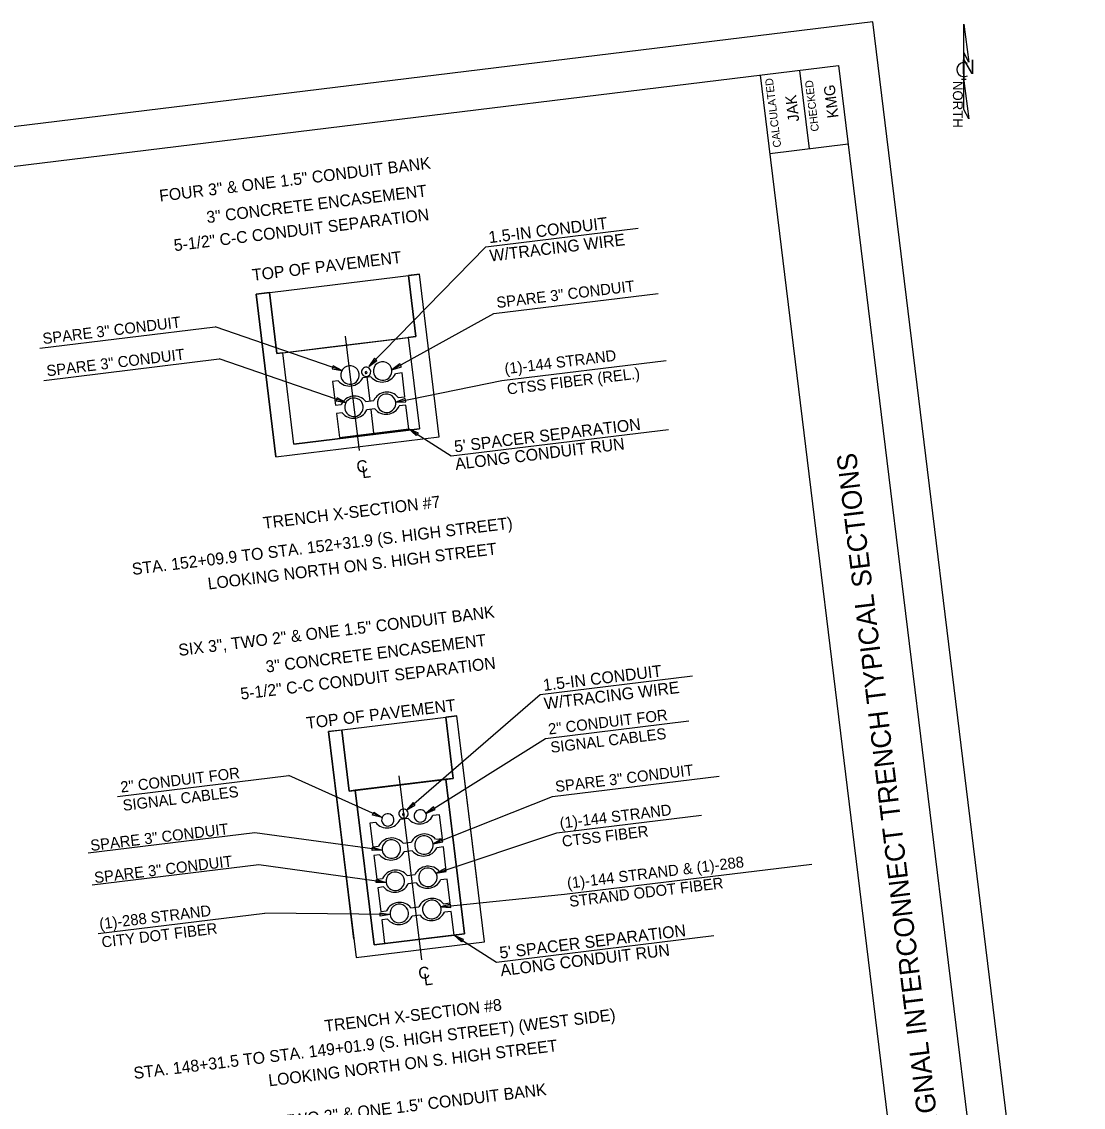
# Model space of a CAD drawing. Extents: x 91401 to 1830080, y 35587 to 712188.
# Drawn here: x 1828758 to 1829296, y 711584 to 712134 of the extents above; entities that cross this region are included whole.
import ezdxf

# ---------------------------------------------------------------- set-up
doc = ezdxf.new("R2010")
doc.units = 0
for name, color, linetype in [('Default', 7, 'Continuous'), ('SH_Border', 7, 'Continuous'), ('SH_Cut_Line', 7, 'Continuous'), ('SH_Data', 7, 'Continuous'), ('SH_Text', 7, 'Continuous')]:
    doc.layers.add(name, color=color, linetype=linetype)

# ---------------------------------------------------------------- blocks, each defined once
blk = doc.blocks.new('POINT_DISPLAY')
at = {"layer": 'Default'}
blk.add_line((0, 0), (0, 0), dxfattribs=at)

msp = doc.modelspace()

# ---------------------------------------------------------------- linework, layer by layer
at = {"layer": 'SH_Border'}
for p, q in [((1829234.27, 711273.16), (1829132.46, 712106.97)), ((1829152.31, 712109.39), (1829157.16, 712069.69)), ((1829137.3, 712067.26), (1829177.01, 712072.11))]:
    msp.add_line(p, q, dxfattribs=at)
for points in [[(1829235.72, 712108.85), (1829235.72, 712132.85), (1829238.12, 712113.65), (1829235.72, 712118.45), (1829235.72, 712104.05), (1829238.12, 712084.85), (1829235.72, 712089.65)], [(1827921.45, 711959.1), (1829172.16, 712111.82), (1829273.97, 711278.01), (1828023.26, 711125.29)]]:
    msp.add_lwpolyline(points, close=True, dxfattribs=at)
msp.add_lwpolyline([(1829234.52, 712105.01), (1829236.92, 712105.01)], dxfattribs=at)
msp.add_arc((1829235.72, 712109.81), 3.6, 60.2518, 299.7482, dxfattribs=at)
at = {"layer": 'SH_Cut_Line'}
msp.add_lwpolyline([(1827946.27, 711095.75), (1829296.25, 711260.58), (1829189.59, 712134.09), (1827839.62, 711969.26)], close=True, dxfattribs=at)
at = {"layer": 'SH_Text'}
for p, q in [((1828993.14, 712019.99), (1829070.5, 712029.44)), ((1828933.81, 711959.29), (1828993.14, 712019.99)), ((1828959.55, 712006.06), (1828953.96, 712005.38)), ((1828957.74, 711974.42), (1828953.96, 712005.38)), ((1828969.63, 711923.54), (1828959.55, 712006.06)), ((1828883.43, 711996.77), (1828876.72, 711995.95)), ((1828876.72, 711995.95), (1828886.79, 711913.43)), ((1828887.21, 711965.81), (1828883.43, 711996.77)), ((1828997.28, 711986.05), (1829080.57, 711996.22)), ((1828945.54, 711957.5), (1828997.28, 711986.05)), ((1828766.99, 711968.53), (1828855.94, 711979.39)), ((1828920.25, 711957.23), (1828855.94, 711979.39)), ((1828921.92, 711974.64), (1828929.02, 711916.55)), ((1828953.91, 711973.95), (1828959.56, 711927.63)), ((1828768.99, 711952.2), (1828857.93, 711963.06)), ((1828922.24, 711940.9), (1828857.93, 711963.06)), ((1828890.18, 711966.17), (1828887.21, 711965.81)), ((1828895.84, 711919.85), (1828890.18, 711966.17)), ((1829001.42, 711952.15), (1829084.71, 711962.32)), ((1828947.53, 711941.15), (1829001.42, 711952.15)), ((1828895.84, 711919.85), (1828959.56, 711927.63)), ((1828895.84, 711919.85), (1828959.56, 711927.63)), ((1828895.84, 711919.85), (1828959.56, 711927.63)), ((1828959.56, 711927.63), (1828895.84, 711919.85)), ((1828954.19, 711927.59), (1828975.68, 711913.86)), ((1828975.68, 711913.86), (1829085.88, 711927.32)), ((1828886.79, 711913.43), (1828969.63, 711923.54)), ((1828886.79, 711913.43), (1828969.63, 711923.54)), ((1829020.72, 711792.88), (1829098.09, 711802.33)), ((1828953.05, 711734.21), (1829020.72, 711792.88)), ((1828978.53, 711781.98), (1828972.94, 711781.3)), ((1828976.72, 711750.34), (1828972.94, 711781.3)), ((1828992.52, 711667.39), (1828978.53, 711781.98)), ((1829023.44, 711770.61), (1829096.13, 711779.49)), ((1828920.21, 711774.86), (1828913.5, 711774.04)), ((1828913.5, 711774.04), (1828927.49, 711659.45)), ((1828923.99, 711743.91), (1828920.21, 711774.86)), ((1828962.85, 711732.59), (1829023.44, 711770.61)), ((1828806.48, 711741.18), (1828893.39, 711751.79)), ((1828940.58, 711730.43), (1828893.39, 711751.79)), ((1828949.16, 711751.57), (1828960.54, 711658.33)), ((1828972.88, 711749.88), (1828982.45, 711671.49)), ((1829027.04, 711741.18), (1829111.57, 711751.5)), ((1828926.97, 711744.27), (1828923.99, 711743.91)), ((1828936.54, 711665.88), (1828926.97, 711744.27)), ((1828966.51, 711717.08), (1829027.04, 711741.18)), ((1828974.03, 711740.46), (1828975.88, 711725.31)), ((1828974.86, 711733.61), (1828977.39, 711712.96)), ((1829029.3, 711722.69), (1829102.54, 711731.64)), ((1828876.07, 711722.75), (1828791.54, 711712.43)), ((1828940.62, 711713.92), (1828876.07, 711722.75)), ((1828968.06, 711702.24), (1829029.3, 711722.69)), ((1828878.06, 711706.42), (1828793.53, 711696.1)), ((1828942.62, 711697.59), (1828878.06, 711706.42)), ((1829033.1, 711691.56), (1829158.6, 711706.88)), ((1828970.33, 711685.21), (1829033.1, 711691.56)), ((1828796.52, 711671.65), (1828881.05, 711681.97)), ((1828944.62, 711681.25), (1828881.05, 711681.97)), ((1828982.45, 711671.49), (1828936.54, 711665.88)), ((1828977.15, 711670.84), (1828998.64, 711657.12)), ((1828927.49, 711659.45), (1828992.52, 711667.39)), ((1828998.64, 711657.12), (1829108.85, 711670.57))]:
    msp.add_line(p, q, dxfattribs=at)
for points in [[(1828876.72, 711995.95), (1828947.26, 712004.56), (1828959.55, 712006.06), (1828959.55, 712006.06)], [(1828883.43, 711996.77), (1828887.21, 711965.81), (1828957.74, 711974.42), (1828953.96, 712005.38)], [(1828953.96, 712005.38), (1828957.74, 711974.42), (1828953.91, 711973.95)], [(1828969.63, 711923.54), (1828959.55, 712006.06)], [(1828886.79, 711913.43), (1828876.72, 711995.95)], [(1828890.18, 711966.17), (1828930.75, 711971.13), (1828953.91, 711973.95), (1828959.56, 711927.63)], [(1828890.18, 711966.17), (1828948.56, 711973.3), (1828953.91, 711973.95), (1828959.56, 711927.63)], [(1828890.18, 711966.17), (1828912.93, 711968.95), (1828953.91, 711973.95), (1828959.56, 711927.63)], [(1828895.84, 711919.85), (1828890.18, 711966.17)], [(1828895.84, 711919.85), (1828890.18, 711966.17)], [(1828918.38, 711952.01), (1828915.46, 711951.65), (1828916.93, 711939.61)], [(1828934.88, 711954.02), (1828930.83, 711953.53)], [(1828932.86, 711953.77), (1828934.33, 711941.74)], [(1828948.8, 711943.5), (1828952.19, 711943.92), (1828950.72, 711955.96), (1828947.33, 711955.54)], [(1828932.3, 711941.49), (1828936.35, 711941.98)], [(1828916.93, 711939.61), (1828919.85, 711939.97)], [(1828920.37, 711935.68), (1828917.45, 711935.32), (1828918.92, 711923.28)], [(1828918.92, 711923.28), (1828954.19, 711927.59), (1828952.72, 711939.62), (1828949.33, 711939.21)], [(1828936.88, 711937.69), (1828932.83, 711937.2)], [(1828934.85, 711937.44), (1828936.32, 711925.41)], [(1828913.5, 711774.04), (1828966.23, 711780.48), (1828978.53, 711781.98), (1828978.53, 711781.98)], [(1828920.21, 711774.86), (1828923.99, 711743.91), (1828976.72, 711750.34), (1828972.94, 711781.3)], [(1828972.94, 711781.3), (1828976.72, 711750.34), (1828972.88, 711749.88)], [(1828988.6, 711699.46), (1828978.53, 711781.98)], [(1828923.58, 711691.52), (1828913.5, 711774.04)], [(1828926.97, 711744.27), (1828949.72, 711747.05), (1828972.88, 711749.88), (1828978.53, 711703.56)], [(1828932.62, 711697.95), (1828926.97, 711744.27)], [(1828967.78, 711719.43), (1828971.17, 711719.84), (1828969.7, 711731.88), (1828966.31, 711731.46)], [(1828937.35, 711727.93), (1828934.43, 711727.57), (1828935.9, 711715.53)], [(1828953.86, 711729.94), (1828949.8, 711729.45)], [(1828926.35, 711668.86), (1828920.69, 711715.18)], [(1828935.9, 711715.53), (1828938.82, 711715.89)], [(1828951.27, 711717.41), (1828955.33, 711717.91)], [(1828969.77, 711703.09), (1828973.16, 711703.5), (1828971.69, 711715.54), (1828968.3, 711715.12)], [(1828939.35, 711711.59), (1828936.42, 711711.23), (1828937.89, 711699.19)], [(1828955.85, 711713.6), (1828951.8, 711713.11)], [(1828937.89, 711699.19), (1828940.82, 711699.55)], [(1828953.27, 711701.07), (1828957.32, 711701.57)], [(1828971.77, 711686.76), (1828975.15, 711687.17), (1828973.69, 711699.21), (1828970.3, 711698.79)], [(1828941.34, 711695.26), (1828938.42, 711694.9), (1828939.89, 711682.86)], [(1828957.85, 711697.27), (1828953.79, 711696.78)], [(1828939.89, 711682.86), (1828942.81, 711683.22)], [(1828941.88, 711666.53), (1828977.15, 711670.84), (1828975.68, 711682.88), (1828972.29, 711682.46)], [(1828955.26, 711684.74), (1828959.32, 711685.24)], [(1828943.34, 711678.93), (1828940.41, 711678.57), (1828941.88, 711666.53)], [(1828959.84, 711680.94), (1828955.79, 711680.45)]]:
    msp.add_lwpolyline(points, dxfattribs=at)
for points in [[(1828937.93, 711962.25), (1828936.74, 711963.42), (1828933.81, 711959.29)], [(1828915.79, 711959.64), (1828915.25, 711958.07), (1828920.25, 711957.23)], [(1828950.37, 711959.02), (1828949.62, 711960.5), (1828945.54, 711957.5)], [(1828917.78, 711943.31), (1828917.24, 711941.74), (1828922.24, 711940.9)], [(1828952.6, 711941.35), (1828952.26, 711942.98), (1828947.53, 711941.15)], [(1828958.85, 711925.59), (1828957.95, 711924.19), (1828954.19, 711927.59)], [(1828936.54, 711665.88), (1828982.45, 711671.49), (1828972.88, 711749.88), (1828926.97, 711744.27)], [(1828957.39, 711736.82), (1828956.31, 711738.08), (1828953.05, 711734.21)], [(1828935.68, 711731.73), (1828936.37, 711733.25), (1828940.58, 711730.43)], [(1828967.54, 711734.51), (1828966.67, 711735.93), (1828962.85, 711732.59)], [(1828935.56, 711713.77), (1828935.78, 711715.42), (1828940.62, 711713.92)], [(1828971.46, 711718.15), (1828970.84, 711719.7), (1828966.51, 711717.08)], [(1828973.06, 711703.03), (1828972.54, 711704.61), (1828968.06, 711702.24)], [(1828937.55, 711697.44), (1828937.78, 711699.09), (1828942.62, 711697.59)], [(1828939.61, 711680.47), (1828939.63, 711682.14), (1828944.62, 711681.25)], [(1828975.39, 711684.89), (1828975.22, 711686.55), (1828970.33, 711685.21)], [(1828981.81, 711668.84), (1828980.91, 711667.44), (1828977.15, 711670.84)]]:
    msp.add_lwpolyline(points, close=True, dxfattribs=at)
for centre, radius, start, end in [((1828924.33, 711954.91), 4.7, 6.9614, 186.9614), ((1828932.53, 711956.51), 2.35, 6.9614, 186.9614), ((1828940.87, 711956.93), 4.7, 6.9614, 186.9614), ((1828940.87, 711956.93), 4.7, 186.9614, 6.9614), ((1828924.12, 711956.76), 7.45, 219.6485, 334.2743), ((1828924.33, 711954.91), 4.7, 186.9614, 6.9614), ((1828932.53, 711956.51), 2.35, 186.9614, 6.9614), ((1828932.51, 711956.11), 0.5, 6.9614, 186.9614), ((1828932.51, 711956.11), 0.5, 186.9614, 6.9614), ((1828940.62, 711958.78), 7.45, 219.6485, 334.2743), ((1828943.07, 711938.75), 7.45, 39.6485, 154.2743), ((1828926.56, 711936.73), 7.45, 39.6485, 154.2743), ((1828926.33, 711938.57), 4.7, 6.9614, 186.9614), ((1828942.87, 711940.58), 4.7, 6.9614, 186.9614), ((1828942.87, 711940.58), 4.7, 186.9614, 6.9614), ((1828926.11, 711940.43), 7.45, 219.6485, 334.2743), ((1828926.33, 711938.57), 4.7, 186.9614, 6.9614), ((1828942.62, 711942.45), 7.45, 219.6485, 334.2743), ((1828943.49, 711729.27), 3.13, 6.9614, 186.9614), ((1828951.5, 711732.44), 2.35, 6.9614, 186.9614), ((1828951.5, 711732.44), 2.35, 186.9614, 6.9614), ((1828951.48, 711732.03), 0.5, 6.9614, 186.9614), ((1828951.48, 711732.03), 0.5, 186.9614, 6.9614), ((1828959.59, 711734.7), 7.45, 219.6485, 334.2743), ((1828960, 711731.29), 3.13, 6.9614, 186.9614), ((1828960, 711731.29), 3.13, 186.9614, 6.9614), ((1828943.09, 711732.68), 7.45, 219.6485, 334.2743), ((1828943.49, 711729.27), 3.13, 186.9614, 6.9614), ((1828962.04, 711714.67), 7.45, 39.6485, 154.2743), ((1828961.84, 711716.51), 4.7, 6.9614, 186.9614), ((1828945.54, 711712.66), 7.45, 39.6485, 154.2743), ((1828945.3, 711714.49), 4.7, 6.9614, 186.9614), ((1828945.3, 711714.49), 4.7, 186.9614, 6.9614), ((1828961.59, 711718.36), 7.45, 219.6485, 334.2743), ((1828961.84, 711716.51), 4.7, 186.9614, 6.9614), ((1828945.09, 711716.34), 7.45, 219.6485, 334.2743), ((1828964.04, 711698.33), 7.45, 39.6485, 154.2743), ((1828963.84, 711700.18), 4.7, 6.9614, 186.9614), ((1828947.53, 711696.32), 7.45, 39.6485, 154.2743), ((1828947.29, 711698.16), 4.7, 6.9614, 186.9614), ((1828947.29, 711698.16), 4.7, 186.9614, 6.9614), ((1828963.58, 711702.03), 7.45, 219.6485, 334.2743), ((1828963.84, 711700.18), 4.7, 186.9614, 6.9614), ((1828947.08, 711700.01), 7.45, 219.6485, 334.2743), ((1828949.53, 711679.99), 7.45, 39.6485, 154.2743), ((1828966.03, 711682), 7.45, 39.6485, 154.2743), ((1828965.83, 711683.84), 4.7, 6.9614, 186.9614), ((1828949.29, 711681.82), 4.7, 6.9614, 186.9614), ((1828949.29, 711681.82), 4.7, 186.9614, 6.9614), ((1828965.58, 711685.7), 7.45, 219.6485, 334.2743), ((1828965.83, 711683.84), 4.7, 186.9614, 6.9614), ((1828949.07, 711683.68), 7.45, 219.6485, 334.2743)]:
    msp.add_arc(centre, radius, start, end, dxfattribs=at)

# ---------------------------------------------------------------- block references
at = {"layer": 'SH_Text', "xscale": 1.5748, "yscale": 1.5748000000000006, "rotation": 6.96142799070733}
for p in [(1828928.18, 711923.41), (1828959.83, 711663)]:
    msp.add_blockref('POINT_DISPLAY', p, dxfattribs=at)

# ---------------------------------------------------------------- texts
at = {"layer": 'SH_Border'}
msp.add_text('N', height=7.2, dxfattribs=at).set_placement((1829234.31, 712107.65))
msp.add_text('NORTH', height=5, rotation=270, dxfattribs=at).set_placement((1829230.12, 712104.05))
at = {"layer": 'SH_Data'}
for s, height, p in [('CALCULATED', 4, (1829143.05, 712070.57)), ('CHECKED', 4, (1829162.2, 712078.68)), ('KMG', 5.6, (1829172.14, 712085.55)), ('JAK', 5.6, (1829152.22, 712083.68)), ('TRAFFIC SIGNAL INTERCONNECT TRENCH TYPICAL SECTIONS', 10, (1829230.69, 711508.69))]:
    msp.add_text(s, height=height, rotation=96.9614, dxfattribs=at).set_placement(p)
at = {"layer": 'SH_Text'}
for s, height, p in [('FOUR 3" & ONE 1.5" CONDUIT BANK', 6, (1828827.97, 712042.8)), ('3" CONCRETE ENCASEMENT', 6, (1828851.89, 712031.91)), ('5-1/2" C-C CONDUIT SEPARATION', 6, (1828835.35, 712017.69)), ('1.5-IN CONDUIT', 6, (1828995.01, 712021.75)), ('W/TRACING WIRE', 6, (1828995.52, 712012.4)), ('TOP OF PAVEMENT', 6, (1828875.05, 712002.59)), ('SPARE 3" CONDUIT', 5.6, (1828998.94, 711988.85)), ('SPARE 3" CONDUIT', 5.6, (1828768.75, 711970.55)), ('SPARE 3" CONDUIT', 5.6, (1828770.75, 711954.22)), ('(1)-144 STRAND', 5.6, (1829003.04, 711955.28)), ('CTSS FIBER (REL.)', 5.6, (1829004.31, 711944.95)), ("5' SPACER SEPARATION", 6, (1828977.56, 711915.62)), ('ALONG CONDUIT RUN', 6, (1828978, 711906.74)), ('C', 6, (1828927.97, 711905.32)), ('L', 6, (1828930.66, 711902.52)), ('TRENCH X-SECTION #7', 6, (1828880.61, 711876.86)), ('STA. 152+09.9 TO STA. 152+31.9 (S. HIGH STREET)', 6, (1828814.1, 711853.47)), ('LOOKING NORTH ON S. HIGH STREET', 6, (1828852.56, 711846.08)), ('SIX 3", TWO 2" & ONE 1.5" CONDUIT BANK', 6, (1828837.67, 711812.4)), ('3" CONCRETE ENCASEMENT', 6, (1828881.94, 711803.99)), ('5-1/2" C-C CONDUIT SEPARATION', 6, (1828869.11, 711790.23)), ('1.5-IN CONDUIT', 6, (1829022.6, 711794.64)), ('W/TRACING WIRE', 6, (1829023.11, 711785.29)), ('TOP OF PAVEMENT', 6, (1828902.53, 711775.41)), ('2" CONDUIT FOR ', 5.6, (1829025.22, 711772.52)), ('SIGNAL CABLES', 5.6, (1829026.35, 711763.25)), ('2" CONDUIT FOR ', 5.6, (1828808.26, 711743.09)), ('SPARE 3" CONDUIT', 5.6, (1829028.78, 711743.36)), ('SIGNAL CABLES', 5.6, (1828809.39, 711733.82)), ('(1)-144 STRAND ', 5.6, (1829031.04, 711724.84)), ('SPARE 3" CONDUIT', 5.6, (1828792.99, 711713.49)), ('CTSS FIBER', 5.6, (1829032.17, 711715.57)), ('SPARE 3" CONDUIT', 5.6, (1828794.98, 711697.16)), ('(1)-144 STRAND & (1)-288 ', 5.6, (1829034.76, 711694.36)), ('STRAND ODOT FIBER', 5.6, (1829035.89, 711685.1)), ('(1)-288 STRAND ', 5.6, (1828797.54, 711673.73)), ('CITY DOT FIBER', 5.6, (1828798.67, 711664.46)), ("5' SPACER SEPARATION", 6, (1829000.52, 711658.87)), ('ALONG CONDUIT RUN', 6, (1829000.97, 711649.99)), ('C', 6, (1828959.34, 711648.39)), ('L', 6, (1828962.08, 711645.21)), ('TRENCH X-SECTION #8', 6, (1828911.76, 711621.73)), ('STA. 148+31.5 TO STA. 149+01.9 (S. HIGH STREET) (WEST SIDE)', 6, (1828814.94, 711597.85)), ('LOOKING NORTH ON S. HIGH STREET', 6, (1828883.33, 711594.11)), ('SIX 3" & TWO 2" & ONE 1.5" CONDUIT BANK', 6, (1828858.69, 711569.54))]:
    msp.add_text(s, height=height, rotation=6.9614, dxfattribs=at).set_placement(p)

doc.saveas('drawing.dxf')
